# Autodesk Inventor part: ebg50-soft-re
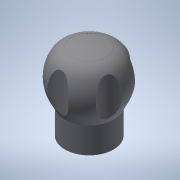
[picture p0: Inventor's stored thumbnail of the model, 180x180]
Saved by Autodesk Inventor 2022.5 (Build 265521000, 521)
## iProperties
Created: 2016-12
Part Number: ebg50-soft-re
Material: 一般
Document SubType Name: Modeling
Designer: imaocorp
Density: 1 g/cm^3
Appearance: 既定
Author: imaocorp
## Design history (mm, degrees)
node "ebg50-soft-re.x_t1"
node "ebg50-soft-re"
node "Base1"
